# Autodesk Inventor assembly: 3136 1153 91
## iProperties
Shininess: 0.0
Length Units: 11269
Angle Units: 11279
Time Units: 11290
Mass Units: 11283
Length Display Precision: 3
Angle Display Precision: 2
Compacted: True
Created: 2000-11
Part Number: 3136 1153 91
Description: Protective arch
Document SubType Name: Assembly
Designer: Joe M
Engineer: Joe M
Density: 0.0
Volumn: 0.0
Area: 0.0
PropertySet Name: Model Information
Control State: 0
Master: False
Checked Out: False
Last Check In By: brjdn
Last Check In Date: 2002-03-12
Title: Störtbåge
Author: Joe M
